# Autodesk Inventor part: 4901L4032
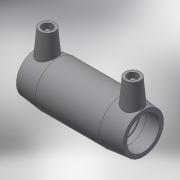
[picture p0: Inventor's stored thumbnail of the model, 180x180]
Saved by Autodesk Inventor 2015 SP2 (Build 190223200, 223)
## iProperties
Created: 2017-06
Part Number: 4901L4032
Material: Generic
Description: PLASSON LONG COUPLER 32
Document SubType Name: Modeling
Designer: KIM
Mass: 72.9589 g
Surface Area: 285.531 cm^2
Volume: 72.9589 cm^3
Density: 1 g/cm^3
Appearance: Default
Author: KIM
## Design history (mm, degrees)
derived "4901L4.ipt"
feature "Solid1::4901L4.ipt"
tag "TaggingFeature1"
body "Solid1"
other parameters: "d0" = 104, "d1" = 32, "d2" = 44, "d4" = 20.8, "d5" = 39.6, "d6" = 25.6, "d7" = 32, "d8" = 168 deg, "d11" = 6.66667, "d29" = 43, "d30" = 15, "d31" = 41.6, "d34" = 5 deg, "d41" = 4, "d42" = 14, "d43" = 0, "d48" = 3, "d49" = 0, "d_" = 32, "L_" = 104, "D_" = 44, "A_" = 43, "d_2" = 12
